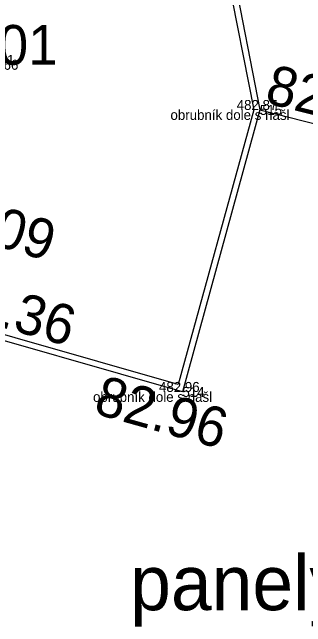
# Model space of a CAD drawing. Extents: x -888468 to -888310, y -1023047 to -1022832.
# Drawn here: x -888380.08 to -888374.18, y -1022915.5 to -1022903.15 of the extents above; entities that cross this region are included whole.
import ezdxf

# ---------------------------------------------------------------- set-up
doc = ezdxf.new("R2010")
doc.units = 0
for name, color, linetype in [('035-spod', 7, 'Continuous'), ('1 hrana zpevněné komunikace-plocha', 7, 'Continuous'), ('4 obrubník dole', 7, 'Continuous'), ('83 semafor', 7, 'Continuous'), ('bod', 7, 'Continuous'), ('bod kod', 7, 'Continuous'), ('bod výška', 7, 'Continuous'), ('bod číslo', 7, 'Continuous'), ('Nadmořská výška TISK', 7, 'Continuous'), ('popisy', 7, 'Continuous')]:
    doc.layers.add(name, color=color, linetype=linetype)

msp = doc.modelspace()

# ---------------------------------------------------------------- linework, layer by layer
at = {"layer": '035-spod'}
for p, q in [((-888375.102, -1022905.111), (-888375.102, -1022905.111)), ((-888375.102, -1022905.111), (-888375.102, -1022905.111)), ((-888375.102, -1022905.111), (-888375.102, -1022905.111)), ((-888375.102, -1022905.111), (-888375.102, -1022905.111)), ((-888376.659, -1022910.778), (-888376.659, -1022910.778)), ((-888376.659, -1022910.778), (-888376.659, -1022910.778)), ((-888376.659, -1022910.778), (-888376.659, -1022910.778)), ((-888376.659, -1022910.778), (-888376.659, -1022910.778))]:
    msp.add_line(p, q, dxfattribs=at)
at = {"layer": '1 hrana zpevněné komunikace-plocha'}
msp.add_lwpolyline([(-888375.102, -1022905.111), (-888370.21, -1022906.346), (-888370.143, -1022906.258)], dxfattribs=at)
at = {"layer": '4 obrubník dole'}
for points in [[(-888392.546, -1022903.598), (-888389.974, -1022896.513), (-888385.953, -1022895.812), (-888382.363, -1022896.397), (-888380.214, -1022897.438), (-888377.917, -1022898.916), (-888376.593, -1022900.48), (-888375.647, -1022902.314), (-888375.102, -1022905.111), (-888376.659, -1022910.778), (-888381.674, -1022909.345)], [(-888392.471, -1022903.743), (-888389.885, -1022896.619), (-888385.952, -1022895.934), (-888382.4, -1022896.513), (-888380.273, -1022897.543), (-888377.997, -1022899.007), (-888376.693, -1022900.547), (-888375.762, -1022902.354), (-888375.225, -1022905.106), (-888376.743, -1022910.629), (-888381.641, -1022909.23)]]:
    msp.add_lwpolyline(points, dxfattribs=at)
at = {"layer": '83 semafor'}
for p, q in [((-888375.102, -1022905.111), (-888375.102, -1022905.111)), ((-888376.659, -1022910.778), (-888376.659, -1022910.778))]:
    msp.add_line(p, q, dxfattribs=at)
at = {"layer": 'bod'}
for p, q in [((-888375.102, -1022905.111), (-888375.102, -1022905.111)), ((-888376.659, -1022910.778), (-888376.659, -1022910.778))]:
    msp.add_line(p, q, dxfattribs=at)

# ---------------------------------------------------------------- texts
at = {"layer": 'bod kod'}
for p in [(-888376.899, -1022905.311), (-888378.456, -1022910.978)]:
    msp.add_text('obrubník dole s nášl', height=0.2, dxfattribs=at).set_placement(p)
at = {"layer": 'bod výška'}
for s, p in [('483.01', (-888380.854, -1022904.204)), ('482.87', (-888375.567, -1022905.111)), ('482.96', (-888377.13, -1022910.778))]:
    msp.add_text(s, height=0.2, dxfattribs=at).set_placement(p)
at = {"layer": 'bod číslo'}
for s, p in [('566', (-888380.404, -1022904.304)), ('515', (-888375.102, -1022905.211)), ('514', (-888376.659, -1022910.878))]:
    msp.add_text(s, height=0.2, dxfattribs=at).set_placement(p)
at = {"layer": 'Nadmořská výška TISK'}
msp.add_text('83.01', height=0.8, dxfattribs=at).set_placement((-888381.843, -1022904.204))
for s, rotation, p in [('82.87', 345.927, (-888375.027, -1022904.962)), ('83.09', 343.293, (-888381.928, -1022907.384)), ('83.36', 344.0531, (-888381.525, -1022909.13)), ('82.96', 344.3101, (-888378.469, -1022911.203))]:
    msp.add_text(s, height=0.8, rotation=rotation, dxfattribs=at).set_placement(p)
at = {"layer": 'popisy'}
msp.add_text('panely', height=1.1016, dxfattribs=at).set_placement((-888377.709, -1022915.165))

doc.saveas('drawing.dxf')
